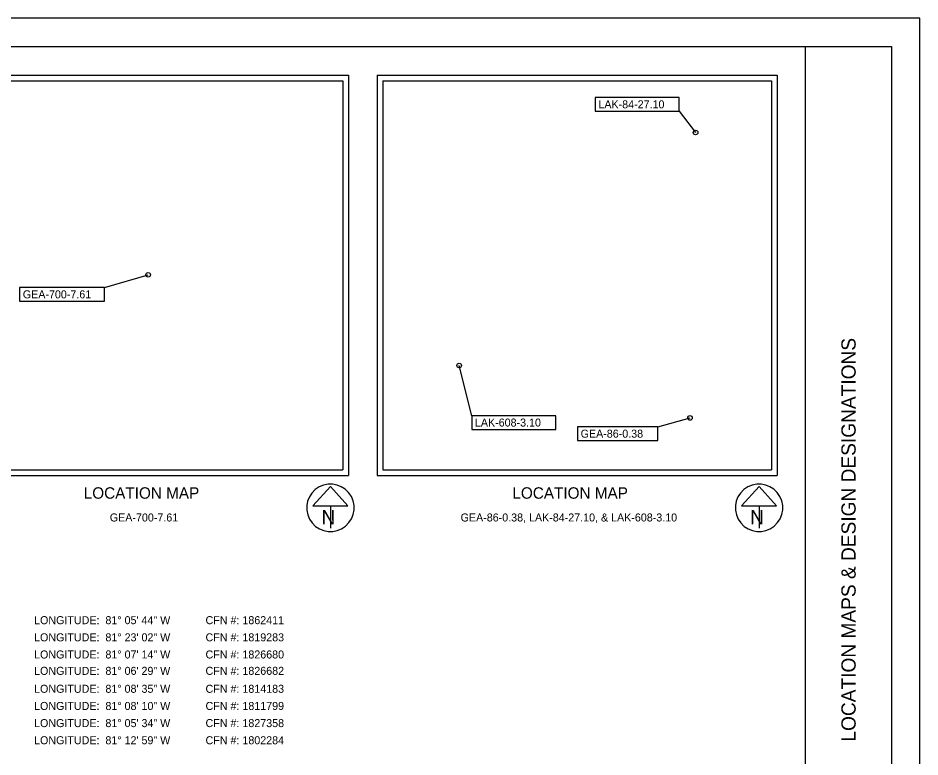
# Model space of a CAD drawing. Extents: x -0.2 to 34, y 0 to 22.
# Drawn here: x 18.22 to 34, y 9.08 to 22 of the extents above; entities that cross this region are included whole.
import ezdxf

# ---------------------------------------------------------------- set-up
doc = ezdxf.new("R2010")
doc.units = 0
for name, color, linetype in [('SH_Border', 7, 'Continuous'), ('SH_Cut_Line', 7, 'Continuous'), ('SH_Data', 7, 'Continuous'), ('SH_Text', 7, 'Continuous')]:
    doc.layers.add(name, color=color, linetype=linetype)

msp = doc.modelspace()

# ---------------------------------------------------------------- linework, layer by layer
at = {"layer": 'SH_Border'}
msp.add_line((32, 0.5), (32, 21.5), dxfattribs=at)
msp.add_lwpolyline([(1.5, 21.5), (33.5, 21.5), (33.5, 0.5), (1.5, 0.5)], close=True, dxfattribs=at)
at = {"layer": 'SH_Cut_Line'}
msp.add_lwpolyline([(0, 0), (34, 0), (34, 22), (0, 22)], close=True, dxfattribs=at)
at = {"layer": 'SH_Data'}
for p, q in [((17, 21), (24, 21)), ((24, 21), (24, 14)), ((24.5, 21), (31.5, 21)), ((24.5, 21), (24.5, 14)), ((31.5, 21), (31.5, 14)), ((17.1, 20.9), (23.9, 20.9)), ((23.9, 20.9), (23.9, 14.1)), ((24.6, 20.9), (24.6, 14.1)), ((24.6, 20.9), (31.4, 20.9)), ((31.4, 20.9), (31.4, 14.1)), ((17.1, 14.1), (23.9, 14.1)), ((24.6, 14.1), (31.4, 14.1)), ((17, 14), (24, 14)), ((24.5, 14), (31.5, 14)), ((23.685, 13.809), (23.377, 13.468)), ((23.992, 13.468), (23.685, 13.809)), ((31.185, 13.809), (30.877, 13.468)), ((31.492, 13.468), (31.185, 13.809)), ((23.377, 13.468), (23.992, 13.468)), ((23.685, 13.468), (23.685, 13.081)), ((23.685, 13.435), (23.685, 13.435)), ((23.685, 13.435), (23.685, 13.435)), ((30.877, 13.468), (31.492, 13.468)), ((31.185, 13.468), (31.185, 13.081)), ((31.185, 13.435), (31.185, 13.435)), ((31.185, 13.435), (31.185, 13.435))]:
    msp.add_line(p, q, dxfattribs=at)
for centre in [(23.685, 13.435), (31.185, 13.435)]:
    msp.add_arc(centre, 0.415, 129.7798, 129.7633, dxfattribs=at)
at = {"layer": 'SH_Text'}
for p, q in [((29.788, 20.371), (30.074, 19.998)), ((19.733, 17.288), (20.497, 17.51)), ((26.158, 15.046), (25.937, 15.923)), ((29.412, 14.852), (29.977, 15.007))]:
    msp.add_line(p, q, dxfattribs=at)
for points in [[(28.319, 20.611), (28.319, 20.371), (29.788, 20.371), (29.788, 20.611)], [(18.247, 17.288), (18.247, 17.048), (19.733, 17.048), (19.733, 17.288)], [(26.158, 15.046), (26.158, 14.806), (27.627, 14.806), (27.627, 15.046)], [(28.008, 14.852), (28.008, 14.612), (29.412, 14.612), (29.412, 14.852)]]:
    msp.add_lwpolyline(points, close=True, dxfattribs=at)
for centre in [(30.074, 19.998), (20.497, 17.51), (25.937, 15.923), (29.977, 15.007)]:
    msp.add_circle(centre, 0.04, dxfattribs=at)

# ---------------------------------------------------------------- texts
at = {"layer": 'SH_Data'}
msp.add_text('LOCATION MAPS & DESIGN DESIGNATIONS', height=0.25, rotation=90, dxfattribs=at).set_placement((32.875, 9.347))
for p in [(23.529, 13.144), (31.029, 13.144)]:
    msp.add_text('N', height=0.25, dxfattribs=at).set_placement(p)
at = {"layer": 'SH_Text'}
for s, height, p in [('LAK-84-27.10', 0.14, (28.374, 20.421)), ('GEA-700-7.61', 0.14, (18.303, 17.098)), ('LAK-608-3.10', 0.14, (26.213, 14.856)), ('GEA-86-0.38', 0.14, (28.063, 14.662)), ('LOCATION MAP', 0.2, (19.369, 13.594)), ('LOCATION MAP', 0.2, (26.869, 13.594)), ('GEA-700-7.61', 0.14, (19.825, 13.196)), ('GEA-86-0.38, LAK-84-27.10, & LAK-608-3.10', 0.14, (25.963, 13.196)), ('LONGITUDE:  81° 05\' 44" W', 0.14, (18.5, 11.4)), ('CFN #: 1862411', 0.14, (21.5, 11.4)), ('LONGITUDE:  81° 23\' 02" W', 0.14, (18.5, 11.1)), ('CFN #: 1819283', 0.14, (21.5, 11.1)), ('LONGITUDE:  81° 07\' 14" W', 0.14, (18.5, 10.8)), ('CFN #: 1826680', 0.14, (21.5, 10.8)), ('LONGITUDE:  81° 06\' 29" W', 0.14, (18.5, 10.514)), ('CFN #: 1826682', 0.14, (21.5, 10.514)), ('LONGITUDE:  81° 08\' 35" W', 0.14, (18.5, 10.2)), ('CFN #: 1814183', 0.14, (21.5, 10.2)), ('LONGITUDE:  81° 08\' 10" W', 0.14, (18.5, 9.9)), ('CFN #: 1811799', 0.14, (21.5, 9.9)), ('LONGITUDE:  81° 05\' 34" W', 0.14, (18.5, 9.6)), ('CFN #: 1827358', 0.14, (21.5, 9.6)), ('LONGITUDE:  81° 12\' 59" W', 0.14, (18.5, 9.3)), ('CFN #: 1802284', 0.14, (21.5, 9.3))]:
    msp.add_text(s, height=height, dxfattribs=at).set_placement(p)

doc.saveas('drawing.dxf')
